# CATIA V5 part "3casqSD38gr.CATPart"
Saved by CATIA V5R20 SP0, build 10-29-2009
Part number: 3casqSD38gr
Revision: ANY
Definition: UNKNOWN
Nomenclature: 3casqSD38gr
Source: Unknown
Bounding box of the stored display mesh (mm): x -13.8 to 24.2, y -8.25 to 8.25, z -8.25 to 8.25
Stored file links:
  C:\Users\Utente\Desktop\IO LAVORO\3D X SITO CF\CUMSA\3D files SD\SD 3824\3casqSD38gr.CATPart
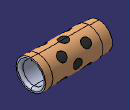
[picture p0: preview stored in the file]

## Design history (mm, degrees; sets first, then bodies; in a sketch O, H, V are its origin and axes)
Body1 "Cortar-Extruir1[1]" (main body)
  Solid1: solid without history
Body2 "Cortar-Extruir1[2]"
  Solid2: solid without history
Body3 "Cortar-Extruir1[3]"
  Solid3: solid without history
Body4 "Cortar-Extruir1[4]"
  Solid4: solid without history
Body5 "Cortar-Extruir1[5]"
  Solid5: solid without history
Body6 "Cortar-Extruir1[6]"
  Solid6: solid without history
Body7 "Cortar-Extruir1[7]"
  Solid7: solid without history
Body8 "Cortar-Extruir1[8]"
  Solid8: solid without history
Body9 "Cortar-Extruir1[9]"
  Solid9: solid without history
Body10 "Cortar-Extruir1[10]"
  Solid10: solid without history
Body11 "Cortar-Extruir1[11]"
  Solid11: solid without history
Body12 "Cortar-Extruir1[12]"
  Solid12: solid without history
Body13 "Cortar-Extruir1[13]"
  Solid13: solid without history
